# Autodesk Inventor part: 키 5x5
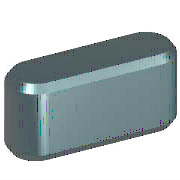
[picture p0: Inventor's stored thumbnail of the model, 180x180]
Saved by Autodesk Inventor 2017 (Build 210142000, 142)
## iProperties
IsCustomPart: 1
Created: 2012-02
Part Number: 키 5x5
Material: 강철, 연강
Description: 키 및 해당 키홈
Document SubType Name: Modeling
Standard: KS B 1311
Designer: mduedu
Standards Organization: KS
Language: ko-KR
Size Designation: 5 x 5 x 12
Categories: <MemberInstance><Categories><Category DisplayName="샤프트 부품" InternalName="7f7aeb1f-a693-4053-b835-cee3144e0d98" Mnemonic="SHFT"><Category DisplayName="키" Interna
Density: 1 g/cm^3
Appearance: 노란색
Author: mduedu
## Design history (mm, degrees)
workplane "Work Plane1"
workplane "Work Plane2"
sketch "스케치1"
  geometry: L1 (2.5, 2.5)-(9.5, 2.5); L2 (9.5, -2.5)-(2.5, -2.5); L3 (0, 9.4)-(0, -7.4) reference; L4 (-5, 0)-(30, 0) reference; L5 (12, 0)-(12, 7); A1 r 2.5 centre (2.5, 0) between (2.5, 2.5) and (2.5, -2.5); A2 r 2.5 centre (9.5, 0) between (9.5, -2.5) and (9.5, 2.5)
  constraints: 6 end point, 5 point on circle, 4 tangent, 3 point on line, 2 centre point, 1 horizontal, 1 parallel, 1 perpendicular
  dimensions: "d0" = 2.5 radius of A1 (= 0.5 x PB); "d13" = 2.5 radius of A2 (= 0.5 x PB); "d14" = 12 distance between parallel lines of L5 L3 (= NLG)
extrude "본체1" new body sketch "스케치1" taper "d3" = 0 deg; stored distance "d4" = 10
workplane "Work Plane3"
body "Solid1"
chamfer "모따기1" distance "d8" = 0.4 (= PHH); stored, may be unused: second distance "d9" = 0.4 (= PHH), angle "d15" = 45 deg
other parameters: "d1" = -3 (= -PNT), "d2" = 2 (= PH - PNT), "NLG" = 12 [user parameter; used in 3 equation terms], "PB" = 5 [user parameter; used in 2 equation terms], "PNT" = 3 [user parameter; used in 2 equation terms], "PH" = 5 [user parameter; used in 1 equation term], "PHH" = 0.4 [user parameter; used in 2 equation terms], "d10" = 0, "d16" = 0, "d17" = 0, "d18" = 0, "WDMIN" = 12 [user parameter], "PLB2" = 12 (= NLG) [user parameter], "WDMAX" = 17 [user parameter], "PLB1" = 12 (= NLG) [user parameter], "RR" = 0.16 [user parameter], "PUEB" = 2.3 [user parameter]
